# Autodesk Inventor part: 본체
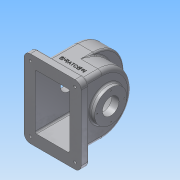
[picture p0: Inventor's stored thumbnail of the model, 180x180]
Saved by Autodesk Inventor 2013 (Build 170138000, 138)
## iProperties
Created: 2017-11
Part Number: 본체
Material: 알루미늄 6061
Document SubType Name: Modeling
Designer: Administrator
Density: 2.71 g/cm^3
Mass: 1079.31 g
Surface Area: 1186.21 cm^2
Volume: 398.271 cm^3
Author: Administrator
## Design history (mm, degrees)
sketch "스케치1"
  geometry: L1 (80, -58)-(15, -58); L2 (80, 58)-(15, 58); L3 (15, 58)-(15, -58); A1 r 58 centre (80, 0) between (80, -58) and (80, 58); 3 further points
  constraints: 6 end point, 2 horizontal alignment, 2 point on circle, 2 tangent, 1 centre point, 1 coincident, 1 horizontal, 1 parallel, 1 perpendicular
  dimensions: "d0" = 116 diameter of A1; "d7" = 15 distance from line of L3 point (0, 0); "d8" = 80 distance of point (0, 0) A1.centre
extrude "돌출1" new body sketch "스케치1" distance "d5" = 39; taper "d6" = 0 deg
sketch "스케치2"
  geometry: L1 (-58, 80)-(-58, 15) reference; L2 (-58, 15)-(58, 15) reference; L3 (58, 15)-(58, 80) reference; A1 r 58 centre (0, 80) between (58, 80) and (-58, 80) reference; A2 r 58 centre (0, 57) between (58, 57) and (-58, 57); 1 further point
  constraints: 2 point on circle, 2 point on line, 1 centre point, 1 vertical alignment
  dimensions: "d9" = 116 diameter of A2; "d11" = 57 distance of point (0, 0) A2.centre
extrude "돌출2" join sketch "스케치2" distance "d12" = 38; taper "d13" = 0 deg
sketch "스케치3"
  geometry: L1 (-94, 75)-(16, 75); L2 (16, 75)-(16, -75); L3 (16, -75)-(-94, -75); L4 (-94, -75)-(-94, 75); L5 (-94, 75)-(16, -75); L6 (16, 75)-(-94, -75); L7 (0, 58)-(0, -58) reference; L8 (0, -58)-(-77, -58) reference; L9 (-77, 58)-(-77, -58) reference; L10 (0, 58)-(-77, 58) reference; L11 (0, -58)-(0, 58) reference; L12 (0, 58)-(-39, 58) reference; L13 (-39, -58)-(-39, 58) reference; L14 (0, -58)-(-39, -58) reference; 2 further points
  constraints: 12 end point, 2 midpoint, 2 parallel, 1 horizontal, 1 perpendicular
  dimensions: "d14" = 110 distance of L2.end L3.end; "d16" = 150 distance of L1.end L2.end; "d17" = 55 horizontal distance of L13.start L2.end; "d18" = 75 distance from line of point (0, 0) L3
extrude "돌출3" join sketch "스케치3" distance "d19" = 15; taper "d20" = 0 deg
feature "쉘1" dims "d21" = 20, "d22" = 5
fillet "모깎기1" dims "d23" = 12, "d24" = 3, "d25" = 8
sketch "스케치4"
  geometry: L1 (63, 0)-(-63, 0) reference; C1 r 37.5 at (0, 65); A1 r 50 centre (0, 80) between (50, 80) and (-50, 80) reference; 1 further point
  constraints: 1 centre point, 1 vertical alignment
  dimensions: "d26" = 75 diameter of C1; "d27" = 65 distance from line of L1 C1.centre
extrude "돌출4" join sketch "스케치4" distance "d28" = 9; taper "d29" = 0 deg
sketch "스케치5"
  geometry: L1 (63, 0)-(-63, 0) reference; C1 r 31 at (0, 65); A1 r 50 centre (0, 57) between (50, 57) and (-50, 57) reference; 1 further point
  constraints: 1 centre point, 1 vertical alignment
  dimensions: "d30" = 62 diameter of C1; "d31" = 65 distance from line of L1 C1.centre
extrude "돌출5" join sketch "스케치5" distance "d32" = 10; taper "d33" = 0 deg
hole "구멍1" diameter "d37" = 32; stored, may be unused: countersink angle "d41" = 90 deg, drill point angle "d43" = 118 deg; dims "d35" = 10, "d36" = 10, "d38" = 6, "d39" = 4, "d40" = 2, "d42" = 8
sketch "스케치6" dims "d44" = 58
  geometry: L1 (0, 0)-(0, 29); C1 r 37.5 at (0, 0) reference; 1 further point
  constraints: 2 end point, 1 coincident, 1 vertical, 1 vertical alignment, 2 other
hole "구멍2" sketch "스케치6" at (0, 29) diameter "d45" = 2.459; stored, may be unused: countersink angle "d49" = 90 deg, drill point angle "d51" = 118 deg; dims "d46" = 6, "d47" = 4, "d48" = 2, "d50" = 8
sketch "스케치7" dims "d55" = 52
  geometry: L1 (0, 0)-(0, 26); C1 r 31 at (0, 0) reference; 1 further point
  constraints: 2 end point, 1 coincident, 1 vertical, 1 vertical alignment, 2 other
hole "구멍3" sketch "스케치7" at (0, 26) diameter "d56" = 2.459; stored, may be unused: countersink angle "d60" = 90 deg, drill point angle "d62" = 118 deg; dims "d57" = 6, "d58" = 4, "d59" = 2, "d61" = 8
node "작업 평면1"
sketch "스케치8"
  geometry: C1 r 6 at (-19, 0); 1 further point
  constraints: 1 centre point, 1 horizontal alignment
  dimensions: "d67" = 19 distance of C1.centre point (0, 0); "d68" = 12 diameter of C1
extrude "돌출6" join sketch "스케치8" stored distance "d69" = 10; taper "d70" = 0 deg
fillet "모깎기2" dims "d34" = 3
hole "구멍4" diameter "d73" = 4.459; stored, may be unused: countersink angle "d77" = 90 deg, drill point angle "d79" = 118 deg; dims "d71" = 10, "d72" = 10, "d74" = 6, "d75" = 4, "d76" = 2, "d78" = 8
sketch "스케치9"
  geometry: A1 r 9 centre (82, -63) between (82, -72) and (91, -63) reference; A2 r 9 centre (82, 63) between (91, 63) and (82, 72) reference; A3 r 9 centre (-4, 63) between (-4, 72) and (-13, 63) reference; A4 r 9 centre (-4, -63) between (-13, -63) and (-4, -72) reference; 1 further point
hole "구멍5" sketch "스케치9" at (-4, -63), (82, -63), (-4, 63), (82, 63) diameter "d80" = 5; stored, may be unused: countersink angle "d84" = 90 deg, drill point angle "d86" = 0 deg; dims "d81" = 6, "d82" = 12, "d83" = 5, "d85" = 8
sketch "스케치10"
  geometry: L1 (-36, 23)-(-36, -39) reference; L2 (-40, -57)-(-52, -57) reference; 2 further points
  constraints: 1 other
  dimensions: "d87" = 38 distance from line of point (2, -17) L1; "d88" = 40 distance from line of point (2, -17) L2
feature "엠보싱1" sketch "스케치10" dims "d14" = 110, "d16" = 150, "d17" = 55, "d18" = 75, "d89" = 0.5, "d90" = 0
chamfer "모따기1" distance "d91" = 1; stored, may be unused: second distance "d92" = 2, angle "d93" = 45 deg
feature "면 이동1"
node "솔리드1"
pattern_circular "원형 패턴1" dims angle "d53" = 360 deg
pattern_circular "원형 패턴2" dims angle "d64" = 360 deg
node "투영된 루프1"
node "투영된 루프2"
other parameters: "d66" = 144
